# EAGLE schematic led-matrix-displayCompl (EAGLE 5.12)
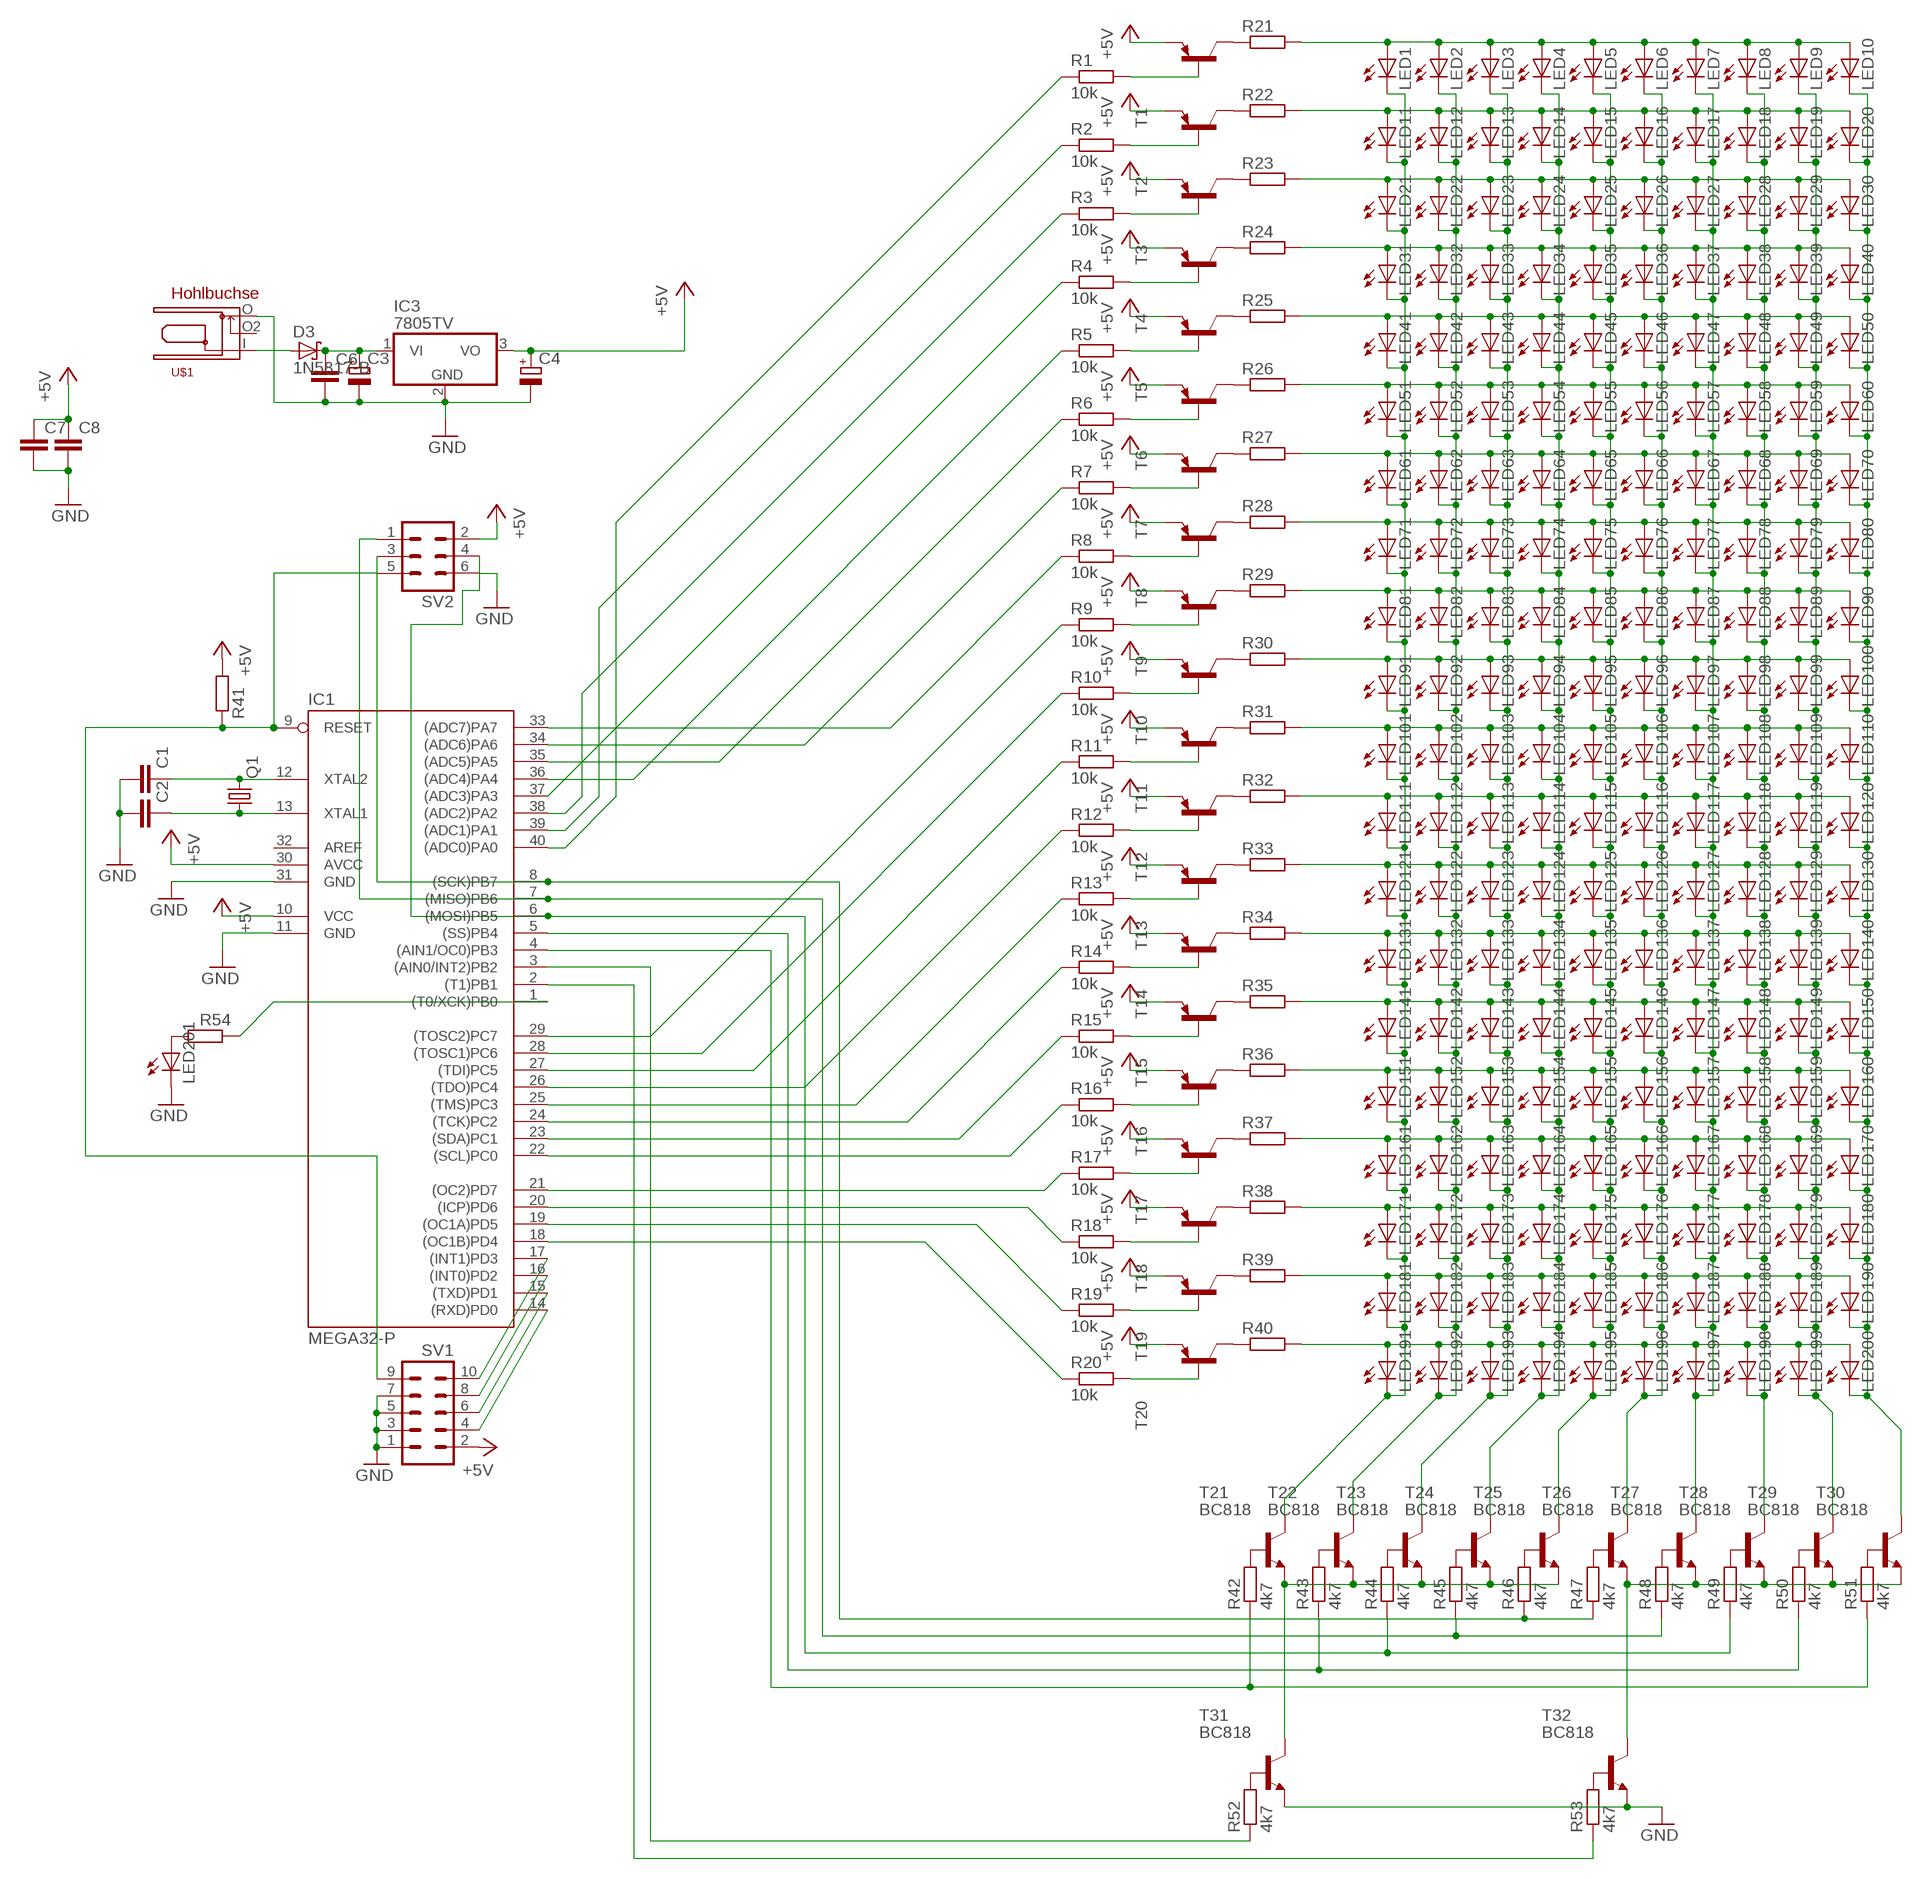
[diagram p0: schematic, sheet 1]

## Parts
C1  C-EUC0805  [C0805]
C2  C-EUC0805  [C0805]
C3  CPOL-EUE2.5-5  [E2,5-5]
C4  CPOL-EUE2.5-5  [E2,5-5]
C6  C-EUC1812K  [C1812K]
C7  C-EUC1812K  [C1812K]
C8  C-EUC1812K  [C1812K]
D3  1N5817-B  [DO41-7.6]
IC1  MEGA32-P  [DIL40]
IC3  7805TV  [TO220V]
LED1  LED3MM  [LED3MM]
LED2  LED3MM  [LED3MM]
LED3  LED3MM  [LED3MM]
LED4  LED3MM  [LED3MM]
LED5  LED3MM  [LED3MM]
LED6  LED3MM  [LED3MM]
LED7  LED3MM  [LED3MM]
LED8  LED3MM  [LED3MM]
LED9  LED3MM  [LED3MM]
LED10  LED3MM  [LED3MM]
LED11  LED3MM  [LED3MM]
LED12  LED3MM  [LED3MM]
LED13  LED3MM  [LED3MM]
LED14  LED3MM  [LED3MM]
LED15  LED3MM  [LED3MM]
LED16  LED3MM  [LED3MM]
LED17  LED3MM  [LED3MM]
LED18  LED3MM  [LED3MM]
LED19  LED3MM  [LED3MM]
LED20  LED3MM  [LED3MM]
LED21  LED3MM  [LED3MM]
LED22  LED3MM  [LED3MM]
LED23  LED3MM  [LED3MM]
LED24  LED3MM  [LED3MM]
LED25  LED3MM  [LED3MM]
LED26  LED3MM  [LED3MM]
LED27  LED3MM  [LED3MM]
LED28  LED3MM  [LED3MM]
LED29  LED3MM  [LED3MM]
LED30  LED3MM  [LED3MM]
LED31  LED3MM  [LED3MM]
LED32  LED3MM  [LED3MM]
LED33  LED3MM  [LED3MM]
LED34  LED3MM  [LED3MM]
LED35  LED3MM  [LED3MM]
LED36  LED3MM  [LED3MM]
LED37  LED3MM  [LED3MM]
LED38  LED3MM  [LED3MM]
LED39  LED3MM  [LED3MM]
LED40  LED3MM  [LED3MM]
LED41  LED3MM  [LED3MM]
LED42  LED3MM  [LED3MM]
LED43  LED3MM  [LED3MM]
LED44  LED3MM  [LED3MM]
LED45  LED3MM  [LED3MM]
LED46  LED3MM  [LED3MM]
LED47  LED3MM  [LED3MM]
LED48  LED3MM  [LED3MM]
LED49  LED3MM  [LED3MM]
LED50  LED3MM  [LED3MM]
LED51  LED3MM  [LED3MM]
LED52  LED3MM  [LED3MM]
LED53  LED3MM  [LED3MM]
LED54  LED3MM  [LED3MM]
LED55  LED3MM  [LED3MM]
LED56  LED3MM  [LED3MM]
LED57  LED3MM  [LED3MM]
LED58  LED3MM  [LED3MM]
LED59  LED3MM  [LED3MM]
LED60  LED3MM  [LED3MM]
LED61  LED3MM  [LED3MM]
LED62  LED3MM  [LED3MM]
LED63  LED3MM  [LED3MM]
LED64  LED3MM  [LED3MM]
LED65  LED3MM  [LED3MM]
LED66  LED3MM  [LED3MM]
LED67  LED3MM  [LED3MM]
LED68  LED3MM  [LED3MM]
LED69  LED3MM  [LED3MM]
LED70  LED3MM  [LED3MM]
LED71  LED3MM  [LED3MM]
LED72  LED3MM  [LED3MM]
LED73  LED3MM  [LED3MM]
LED74  LED3MM  [LED3MM]
LED75  LED3MM  [LED3MM]
LED76  LED3MM  [LED3MM]
LED77  LED3MM  [LED3MM]
LED78  LED3MM  [LED3MM]
LED79  LED3MM  [LED3MM]
LED80  LED3MM  [LED3MM]
LED81  LED3MM  [LED3MM]
LED82  LED3MM  [LED3MM]
LED83  LED3MM  [LED3MM]
LED84  LED3MM  [LED3MM]
LED85  LED3MM  [LED3MM]
LED86  LED3MM  [LED3MM]
LED87  LED3MM  [LED3MM]
LED88  LED3MM  [LED3MM]
LED89  LED3MM  [LED3MM]
LED90  LED3MM  [LED3MM]
LED91  LED3MM  [LED3MM]
LED92  LED3MM  [LED3MM]
LED93  LED3MM  [LED3MM]
LED94  LED3MM  [LED3MM]
LED95  LED3MM  [LED3MM]
LED96  LED3MM  [LED3MM]
LED97  LED3MM  [LED3MM]
LED98  LED3MM  [LED3MM]
LED99  LED3MM  [LED3MM]
LED100  LED3MM  [LED3MM]
LED101  LED3MM  [LED3MM]
LED102  LED3MM  [LED3MM]
LED103  LED3MM  [LED3MM]
LED104  LED3MM  [LED3MM]
LED105  LED3MM  [LED3MM]
LED106  LED3MM  [LED3MM]
LED107  LED3MM  [LED3MM]
LED108  LED3MM  [LED3MM]
LED109  LED3MM  [LED3MM]
LED110  LED3MM  [LED3MM]
LED111  LED3MM  [LED3MM]
LED112  LED3MM  [LED3MM]
LED113  LED3MM  [LED3MM]
LED114  LED3MM  [LED3MM]
LED115  LED3MM  [LED3MM]
LED116  LED3MM  [LED3MM]
LED117  LED3MM  [LED3MM]
LED118  LED3MM  [LED3MM]
LED119  LED3MM  [LED3MM]
LED120  LED3MM  [LED3MM]
LED121  LED3MM  [LED3MM]
LED122  LED3MM  [LED3MM]
LED123  LED3MM  [LED3MM]
LED124  LED3MM  [LED3MM]
LED125  LED3MM  [LED3MM]
LED126  LED3MM  [LED3MM]
LED127  LED3MM  [LED3MM]
LED128  LED3MM  [LED3MM]
LED129  LED3MM  [LED3MM]
LED130  LED3MM  [LED3MM]
LED131  LED3MM  [LED3MM]
LED132  LED3MM  [LED3MM]
LED133  LED3MM  [LED3MM]
LED134  LED3MM  [LED3MM]
LED135  LED3MM  [LED3MM]
LED136  LED3MM  [LED3MM]
LED137  LED3MM  [LED3MM]
LED138  LED3MM  [LED3MM]
LED139  LED3MM  [LED3MM]
LED140  LED3MM  [LED3MM]
LED141  LED3MM  [LED3MM]
LED142  LED3MM  [LED3MM]
LED143  LED3MM  [LED3MM]
LED144  LED3MM  [LED3MM]
LED145  LED3MM  [LED3MM]
LED146  LED3MM  [LED3MM]
LED147  LED3MM  [LED3MM]
LED148  LED3MM  [LED3MM]
LED149  LED3MM  [LED3MM]
LED150  LED3MM  [LED3MM]
LED151  LED3MM  [LED3MM]
LED152  LED3MM  [LED3MM]
LED153  LED3MM  [LED3MM]
LED154  LED3MM  [LED3MM]
LED155  LED3MM  [LED3MM]
LED156  LED3MM  [LED3MM]
LED157  LED3MM  [LED3MM]
LED158  LED3MM  [LED3MM]
LED159  LED3MM  [LED3MM]
LED160  LED3MM  [LED3MM]
LED161  LED3MM  [LED3MM]
LED162  LED3MM  [LED3MM]
LED163  LED3MM  [LED3MM]
LED164  LED3MM  [LED3MM]
LED165  LED3MM  [LED3MM]
LED166  LED3MM  [LED3MM]
LED167  LED3MM  [LED3MM]
LED168  LED3MM  [LED3MM]
LED169  LED3MM  [LED3MM]
LED170  LED3MM  [LED3MM]
LED171  LED3MM  [LED3MM]
LED172  LED3MM  [LED3MM]
LED173  LED3MM  [LED3MM]
LED174  LED3MM  [LED3MM]
LED175  LED3MM  [LED3MM]
LED176  LED3MM  [LED3MM]
LED177  LED3MM  [LED3MM]
LED178  LED3MM  [LED3MM]
LED179  LED3MM  [LED3MM]
LED180  LED3MM  [LED3MM]
LED181  LED3MM  [LED3MM]
LED182  LED3MM  [LED3MM]
LED183  LED3MM  [LED3MM]
LED184  LED3MM  [LED3MM]
LED185  LED3MM  [LED3MM]
LED186  LED3MM  [LED3MM]
LED187  LED3MM  [LED3MM]
LED188  LED3MM  [LED3MM]
LED189  LED3MM  [LED3MM]
LED190  LED3MM  [LED3MM]
LED191  LED3MM  [LED3MM]
LED192  LED3MM  [LED3MM]
LED193  LED3MM  [LED3MM]
LED194  LED3MM  [LED3MM]
LED195  LED3MM  [LED3MM]
LED196  LED3MM  [LED3MM]
LED197  LED3MM  [LED3MM]
LED198  LED3MM  [LED3MM]
LED199  LED3MM  [LED3MM]
LED200  LED3MM  [LED3MM]
LED201  LED5MM  [LED5MM]
Q1  CRYSTALHC49UP  [HC49UP]
R1  10k  R-EU_R0805  [R0805]
R2  10k  R-EU_R0805  [R0805]
R3  10k  R-EU_R0805  [R0805]
R4  10k  R-EU_R0805  [R0805]
R5  10k  R-EU_R0805  [R0805]
R6  10k  R-EU_R0805  [R0805]
R7  10k  R-EU_R0805  [R0805]
R8  10k  R-EU_R0805  [R0805]
R9  10k  R-EU_R0805  [R0805]
R10  10k  R-EU_R0805  [R0805]
R11  10k  R-EU_R0805  [R0805]
R12  10k  R-EU_R0805  [R0805]
R13  10k  R-EU_R0805  [R0805]
R14  10k  R-EU_R0805  [R0805]
R15  10k  R-EU_R0805  [R0805]
R16  10k  R-EU_R0805  [R0805]
R17  10k  R-EU_R0805  [R0805]
R18  10k  R-EU_R0805  [R0805]
R19  10k  R-EU_R0805  [R0805]
R20  10k  R-EU_R0805  [R0805]
R21  R-EU_R1206  [R1206]
R22  R-EU_R1206  [R1206]
R23  R-EU_R1206  [R1206]
R24  R-EU_R1206  [R1206]
R25  R-EU_R1206  [R1206]
R26  R-EU_R1206  [R1206]
R27  R-EU_R1206  [R1206]
R28  R-EU_R1206  [R1206]
R29  R-EU_R1206  [R1206]
R30  R-EU_R1206  [R1206]
R31  R-EU_R1206  [R1206]
R32  R-EU_R1206  [R1206]
R33  R-EU_R1206  [R1206]
R34  R-EU_R1206  [R1206]
R35  R-EU_R1206  [R1206]
R36  R-EU_R1206  [R1206]
R37  R-EU_R1206  [R1206]
R38  R-EU_R1206  [R1206]
R39  R-EU_R1206  [R1206]
R40  R-EU_R1206  [R1206]
R41  R-EU_R0805  [R0805]
R42  4k7  R-EU_R1206  [R1206]
R43  4k7  R-EU_R1206  [R1206]
R44  4k7  R-EU_R1206  [R1206]
R45  4k7  R-EU_R1206  [R1206]
R46  4k7  R-EU_R1206  [R1206]
R47  4k7  R-EU_R1206  [R1206]
R48  4k7  R-EU_R1206  [R1206]
R49  4k7  R-EU_R1206  [R1206]
R50  4k7  R-EU_R1206  [R1206]
R51  4k7  R-EU_R1206  [R1206]
R52  4k7  R-EU_R1206  [R1206]
R53  4k7  R-EU_R1206  [R1206]
R54  R-EU_R0805  [R0805]
SV1  ML10  [ML10]
SV2  ML6  [ML6]
T1  BC856A-PNP-SOT23-BEC  [SOT23-BEC]
T2  BC856A-PNP-SOT23-BEC  [SOT23-BEC]
T3  BC856A-PNP-SOT23-BEC  [SOT23-BEC]
T4  BC856A-PNP-SOT23-BEC  [SOT23-BEC]
T5  BC856A-PNP-SOT23-BEC  [SOT23-BEC]
T6  BC856A-PNP-SOT23-BEC  [SOT23-BEC]
T7  BC856A-PNP-SOT23-BEC  [SOT23-BEC]
T8  BC856A-PNP-SOT23-BEC  [SOT23-BEC]
T9  BC856A-PNP-SOT23-BEC  [SOT23-BEC]
T10  BC856A-PNP-SOT23-BEC  [SOT23-BEC]
T11  BC856A-PNP-SOT23-BEC  [SOT23-BEC]
T12  BC856A-PNP-SOT23-BEC  [SOT23-BEC]
T13  BC856A-PNP-SOT23-BEC  [SOT23-BEC]
T14  BC856A-PNP-SOT23-BEC  [SOT23-BEC]
T15  BC856A-PNP-SOT23-BEC  [SOT23-BEC]
T16  BC856A-PNP-SOT23-BEC  [SOT23-BEC]
T17  BC856A-PNP-SOT23-BEC  [SOT23-BEC]
T18  BC856A-PNP-SOT23-BEC  [SOT23-BEC]
T19  BC856A-PNP-SOT23-BEC  [SOT23-BEC]
T20  BC856A-PNP-SOT23-BEC  [SOT23-BEC]
T21  BC818  BC850  [SOT23]
T22  BC818  BC850  [SOT23]
T23  BC818  BC850  [SOT23]
T24  BC818  BC850  [SOT23]
T25  BC818  BC850  [SOT23]
T26  BC818  BC850  [SOT23]
T27  BC818  BC850  [SOT23]
T28  BC818  BC850  [SOT23]
T29  BC818  BC850  [SOT23]
T30  BC818  BC850  [SOT23]
T31  BC818  BC850  [SOT23]
T32  BC818  BC850  [SOT23]
U$1  HOHLBUCHSE  [HOHLBUCHSE]

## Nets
+5V: C4.+ C7.1 C8.1 IC1.10(VCC) IC1.30(AVCC) IC3.3(VO) R41.2 SV1.2 SV2.2 T1.E T2.E T3.E T4.E T5.E T6.E T7.E T8.E T9.E T10.E T11.E T12.E T13.E T14.E T15.E T16.E T17.E T18.E T19.E T20.E
GND: C1.2 C2.2 C3.- C4.- C6.2 C7.2 C8.2 IC1.11(GND) IC1.31(GND) IC3.2(GND) LED201.K(C) SV1.1 SV1.3 SV1.5 SV1.7 SV2.6 T31.2(E) T32.2(E) U$1.O
N$1: LED1.A LED2.A LED3.A LED4.A LED5.A LED6.A LED7.A LED8.A LED9.A LED10.A R21.2
N$2: LED11.A LED12.A LED13.A LED14.A LED15.A LED16.A LED17.A LED18.A LED19.A LED20.A R22.2
N$3: LED21.A LED22.A LED23.A LED24.A LED25.A LED26.A LED27.A LED28.A LED29.A LED30.A R23.2
N$4: LED31.A LED32.A LED33.A LED34.A LED35.A LED36.A LED37.A LED38.A LED39.A LED40.A R24.2
N$5: LED41.A LED42.A LED43.A LED44.A LED45.A LED46.A LED47.A LED48.A LED49.A LED50.A R25.2
N$6: LED51.A LED52.A LED53.A LED54.A LED55.A LED56.A LED57.A LED58.A LED59.A LED60.A R26.2
N$7: LED61.A LED62.A LED63.A LED64.A LED65.A LED66.A LED67.A LED68.A LED69.A LED70.A R27.2
N$8: LED71.A LED72.A LED73.A LED74.A LED75.A LED76.A LED77.A LED78.A LED79.A LED80.A R28.2
N$9: LED81.A LED82.A LED83.A LED84.A LED85.A LED86.A LED87.A LED88.A LED89.A LED90.A R29.2
N$10: LED91.A LED92.A LED93.A LED94.A LED95.A LED96.A LED97.A LED98.A LED99.A LED100.A R30.2
N$11: LED101.A LED102.A LED103.A LED104.A LED105.A LED106.A LED107.A LED108.A LED109.A LED110.A R31.2
N$12: LED111.A LED112.A LED113.A LED114.A LED115.A LED116.A LED117.A LED118.A LED119.A LED120.A R32.2
N$13: LED121.A LED122.A LED123.A LED124.A LED125.A LED126.A LED127.A LED128.A LED129.A LED130.A R33.2
N$14: IC1.9(RESET) R41.1 SV1.9 SV2.5
N$15: LED141.A LED142.A LED143.A LED144.A LED145.A LED146.A LED147.A LED148.A LED149.A LED150.A R35.2
N$16: LED151.A LED152.A LED153.A LED154.A LED155.A LED156.A LED157.A LED158.A LED159.A LED160.A R36.2
N$17: LED161.A LED162.A LED163.A LED164.A LED165.A LED166.A LED167.A LED168.A LED169.A LED170.A R37.2
N$18: IC1.18((OC1B)PD4) R20.1
N$19: LED181.A LED182.A LED183.A LED184.A LED185.A LED186.A LED187.A LED188.A LED189.A LED190.A R39.2
N$20: IC1.19((OC1A)PD5) R19.1
N$21: LED1.K(C) LED11.K(C) LED21.K(C) LED31.K(C) LED41.K(C) LED51.K(C) LED61.K(C) LED71.K(C) LED81.K(C) LED91.K(C) LED101.K(C) LED111.K(C) LED121.K(C) LED131.K(C) LED141.K(C) LED151.K(C) LED161.K(C) LED171.K(C) LED181.K(C) LED191.K(C) T21.3(C)
N$22: LED2.K(C) LED12.K(C) LED22.K(C) LED32.K(C) LED42.K(C) LED52.K(C) LED62.K(C) LED72.K(C) LED82.K(C) LED92.K(C) LED102.K(C) LED112.K(C) LED122.K(C) LED132.K(C) LED142.K(C) LED152.K(C) LED162.K(C) LED172.K(C) LED182.K(C) LED192.K(C) T22.3(C)
N$23: LED3.K(C) LED13.K(C) LED23.K(C) LED33.K(C) LED43.K(C) LED53.K(C) LED63.K(C) LED73.K(C) LED83.K(C) LED93.K(C) LED103.K(C) LED113.K(C) LED123.K(C) LED133.K(C) LED143.K(C) LED153.K(C) LED163.K(C) LED173.K(C) LED183.K(C) LED193.K(C) T23.3(C)
N$24: LED4.K(C) LED14.K(C) LED24.K(C) LED34.K(C) LED44.K(C) LED54.K(C) LED64.K(C) LED74.K(C) LED84.K(C) LED94.K(C) LED104.K(C) LED114.K(C) LED124.K(C) LED134.K(C) LED144.K(C) LED154.K(C) LED164.K(C) LED174.K(C) LED184.K(C) LED194.K(C) T24.3(C)
N$25: LED5.K(C) LED15.K(C) LED25.K(C) LED35.K(C) LED45.K(C) LED55.K(C) LED65.K(C) LED75.K(C) LED85.K(C) LED95.K(C) LED105.K(C) LED115.K(C) LED125.K(C) LED135.K(C) LED145.K(C) LED155.K(C) LED165.K(C) LED175.K(C) LED185.K(C) LED195.K(C) T25.3(C)
N$26: LED6.K(C) LED16.K(C) LED26.K(C) LED36.K(C) LED46.K(C) LED56.K(C) LED66.K(C) LED76.K(C) LED86.K(C) LED96.K(C) LED106.K(C) LED116.K(C) LED126.K(C) LED136.K(C) LED146.K(C) LED156.K(C) LED166.K(C) LED176.K(C) LED186.K(C) LED196.K(C) T26.3(C)
N$27: LED7.K(C) LED17.K(C) LED27.K(C) LED37.K(C) LED47.K(C) LED57.K(C) LED67.K(C) LED77.K(C) LED87.K(C) LED97.K(C) LED107.K(C) LED117.K(C) LED127.K(C) LED137.K(C) LED147.K(C) LED157.K(C) LED167.K(C) LED177.K(C) LED187.K(C) LED197.K(C) T27.3(C)
N$28: LED8.K(C) LED18.K(C) LED28.K(C) LED38.K(C) LED48.K(C) LED58.K(C) LED68.K(C) LED78.K(C) LED88.K(C) LED98.K(C) LED108.K(C) LED118.K(C) LED128.K(C) LED138.K(C) LED148.K(C) LED158.K(C) LED168.K(C) LED178.K(C) LED188.K(C) LED198.K(C) T28.3(C)
N$29: LED9.K(C) LED19.K(C) LED29.K(C) LED39.K(C) LED49.K(C) LED59.K(C) LED69.K(C) LED79.K(C) LED89.K(C) LED99.K(C) LED109.K(C) LED119.K(C) LED129.K(C) LED139.K(C) LED149.K(C) LED159.K(C) LED169.K(C) LED179.K(C) LED189.K(C) LED199.K(C) T29.3(C)
N$30: LED10.K(C) LED20.K(C) LED30.K(C) LED40.K(C) LED50.K(C) LED60.K(C) LED70.K(C) LED80.K(C) LED90.K(C) LED100.K(C) LED110.K(C) LED120.K(C) LED130.K(C) LED140.K(C) LED150.K(C) LED160.K(C) LED170.K(C) LED180.K(C) LED190.K(C) LED200.K(C) T30.3(C)
N$31: R1.2 T1.B
N$32: R2.2 T2.B
N$33: R3.2 T3.B
N$34: R4.2 T4.B
N$35: R5.2 T5.B
N$36: R6.2 T6.B
N$37: R7.2 T7.B
N$38: R8.2 T8.B
N$39: R9.2 T9.B
N$40: R10.2 T10.B
N$41: R11.2 T11.B
N$42: R12.2 T12.B
N$43: R13.2 T13.B
N$44: R14.2 T14.B
N$45: R15.2 T15.B
N$46: R16.2 T16.B
N$47: R17.2 T17.B
N$48: R18.2 T18.B
N$49: R19.2 T19.B
N$50: R20.2 T20.B
N$51: R21.1 T1.C
N$52: R26.1 T6.C
N$53: R22.1 T2.C
N$54: R23.1 T3.C
N$55: R24.1 T4.C
N$56: R25.1 T5.C
N$57: R27.1 T7.C
N$58: R28.1 T8.C
N$59: R29.1 T9.C
N$60: R30.1 T10.C
N$61: R31.1 T11.C
N$62: R32.1 T12.C
N$63: R33.1 T13.C
N$64: R34.1 T14.C
N$65: R35.1 T15.C
N$66: R36.1 T16.C
N$67: R37.1 T17.C
N$68: R38.1 T18.C
N$69: R39.1 T19.C
N$70: R40.1 T20.C
N$71: LED191.A LED192.A LED193.A LED194.A LED195.A LED196.A LED197.A LED198.A LED199.A LED200.A R40.2
N$72: LED171.A LED172.A LED173.A LED174.A LED175.A LED176.A LED177.A LED178.A LED179.A LED180.A R38.2
N$73: LED131.A LED132.A LED133.A LED134.A LED135.A LED136.A LED137.A LED138.A LED139.A LED140.A R34.2
N$74: IC1.6((MOSI)PB5) R44.1 R49.1 SV2.4
N$75: IC1.7((MISO)PB6) R45.1 R48.1 SV2.1
N$76: IC1.20((ICP)PD6) R18.1
N$77: IC1.21((OC2)PD7) R17.1
N$78: IC1.8((SCK)PB7) R46.1 R47.1 SV2.3
N$79: IC1.22((SCL)PC0) R16.1
N$80: C1.1 IC1.12(XTAL2) Q1.2
N$81: C2.1 IC1.13(XTAL1) Q1.1
N$82: IC1.14((RXD)PD0) SV1.4
N$83: IC1.15((TXD)PD1) SV1.6
N$84: IC1.16((INT0)PD2) SV1.8
N$85: IC1.17((INT1)PD3) SV1.10
N$86: IC1.23((SDA)PC1) R15.1
N$87: IC1.24((TCK)PC2) R14.1
N$88: IC1.25((TMS)PC3) R13.1
N$89: IC1.26((TDO)PC4) R12.1
N$90: IC1.27((TDI)PC5) R11.1
N$91: IC1.28((TOSC1)PC6) R10.1
N$92: C3.+ C6.1 D3.C IC3.1(VI)
N$93: D3.A U$1.I
N$94: R42.2 T21.1(B)
N$95: IC1.29((TOSC2)PC7) R9.1
N$96: IC1.33((ADC7)PA7) R8.1
N$97: IC1.34((ADC6)PA6) R7.1
N$98: IC1.35((ADC5)PA5) R6.1
N$99: IC1.36((ADC4)PA4) R5.1
N$100: IC1.37((ADC3)PA3) R4.1
N$101: IC1.38((ADC2)PA2) R3.1
N$102: IC1.39((ADC1)PA1) R2.1
N$103: IC1.40((ADC0)PA0) R1.1
N$104: R43.2 T22.1(B)
N$105: R44.2 T23.1(B)
N$106: R45.2 T24.1(B)
N$107: R46.2 T25.1(B)
N$108: R47.2 T26.1(B)
N$109: R48.2 T27.1(B)
N$110: R49.2 T28.1(B)
N$111: R50.2 T29.1(B)
N$112: R51.2 T30.1(B)
N$113: R52.2 T31.1(B)
N$114: R53.2 T32.1(B)
N$115: IC1.3((AIN0/INT2)PB2) R52.1
N$116: IC1.5((SS)PB4) R43.1 R50.1
N$117: IC1.4((AIN1/OC0)PB3) R42.1 R51.1
N$118: T21.2(E) T22.2(E) T23.2(E) T24.2(E) T25.2(E) T31.3(C)
N$119: T26.2(E) T27.2(E) T28.2(E) T29.2(E) T30.2(E) T32.3(C)
N$120: IC1.2((T1)PB1) R53.1
N$121: LED201.A R54.2
N$122: IC1.1((T0/XCK)PB0) R54.1
Unconnected: IC1.32(AREF) U$1.O2

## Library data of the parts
C1 C2 C6-C8 = rcl:C-EU: CAPACITOR, European symbol
C3 C4 = rcl:CPOL-EU: POLARIZED CAPACITOR, European symbol
D3 = diode:1N581*: 1.0A SCHOTTKY BARRIER RECTIFIER
IC1 = atmel:MEGA32-P: MICROCONTROLLER 32 Kbytes FLASH 2 Kbytes SRAM 1 Kbytes EEPROM USART 8-channel 10 bit ADC Source: www.atmel.com .. doc2503.pdf; MPN: ATMEGA32-16PU; OC_FARNELL: 1661729; OC_NEWARK: 51P1794
IC3 = linear:78*: Positive VOLTAGE REGULATOR Source: http://cache.national.com/ds/LM/LM78L05.pdf http://www.fairchildsemi.com/ds/LM/LM7805.pdf
LED1-LED201 = led:LED: LED
Q1 = crystal:CRYSTAL: CRYSTAL; OC_FARNELL: unknown; OC_NEWARK: unknown
R1-R54 = rcl:R-EU_: RESISTOR, European symbol
SV1 = con-harting-ml:ML10: HARTING; OC_FARNELL: unknown; OC_NEWARK: unknown
SV2 = con-ml:ML6: HARTING; OC_FARNELL: unknown; OC_NEWARK: unknown
T1-T20 = transistor:*-PNP-: PNP Transistror
T21-T32 = transistor:BC850: NPN TRANSISTOR
U$1 = smdTaster:HOHLBUCHSE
